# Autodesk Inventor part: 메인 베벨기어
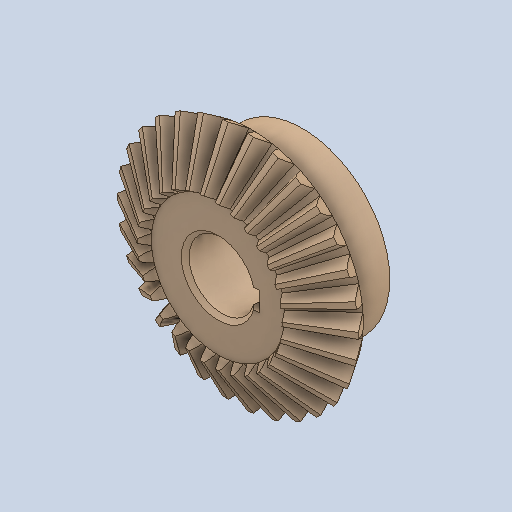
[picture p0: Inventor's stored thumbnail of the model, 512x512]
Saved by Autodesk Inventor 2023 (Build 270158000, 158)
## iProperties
Created: 2025-04
Part Number: 메인 베벨기어
Material: 강철, 탄소
Document SubType Name: Modeling
Designer: Admin
Density: 7.87 g/cm^3
Appearance: 기본값
Author: jhkim
Revision Number: 1
Sending System: Autodesk Inventor 2026
Preprocessor: ST-DEVELOPER v20.1
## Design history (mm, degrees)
feature "Solid1"
node "솔리드1"
